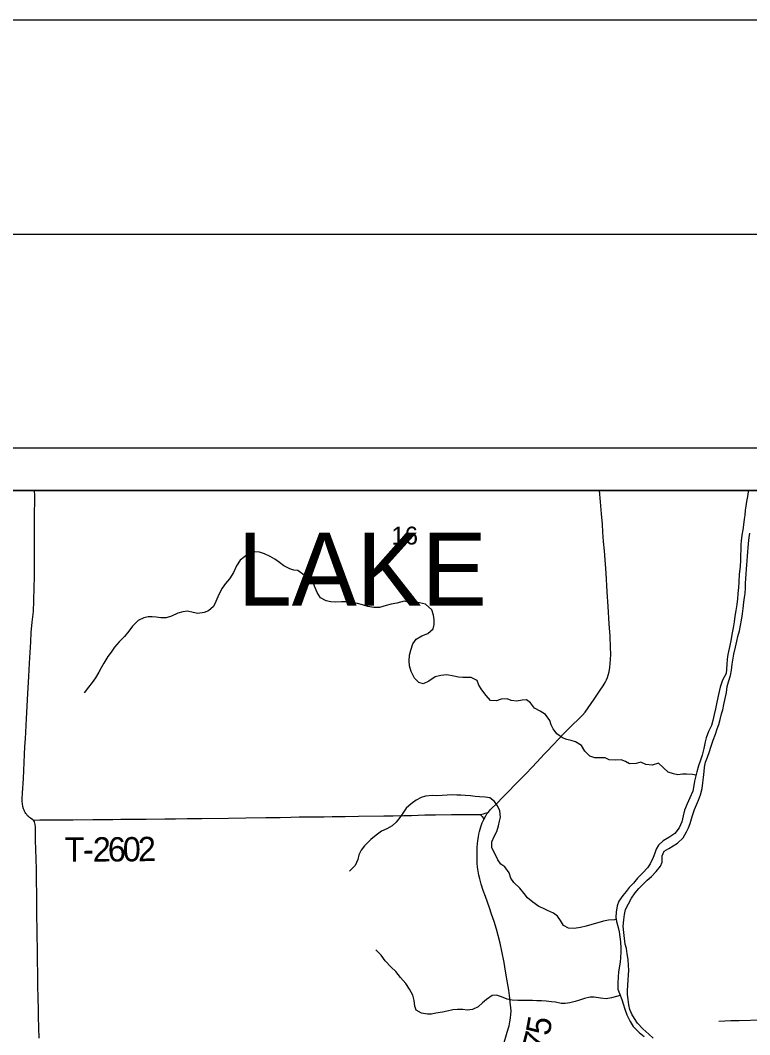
# Model space of a CAD drawing. Extents: x -7.5 to 53.5, y 0 to 22.
# Drawn here: x 6.245 to 7.951, y 19.628 to 22 of the extents above; entities that cross this region are included whole.
import ezdxf

# ---------------------------------------------------------------- set-up
doc = ezdxf.new("R2010")
doc.units = 0
for name, color, linetype in [('GM_X_Corporation', 7, 'Continuous'), ('GM_X_County_Road', 7, 'Continuous'), ('GM_X_County_Road_Text', 7, 'Continuous'), ('GM_X_Major_River', 7, 'Continuous'), ('GM_X_Minor_River', 7, 'Continuous'), ('GM_X_Section_Text', 7, 'Continuous'), ('GM_X_Township_Road', 7, 'Continuous'), ('GM_X_Township_Road_Text', 7, 'Continuous'), ('GM_X_Township_Text', 7, 'Continuous'), ('SH_Border', 7, 'Continuous'), ('SH_Cut_Line', 7, 'Continuous'), ('SH_Data', 7, 'Continuous')]:
    doc.layers.add(name, color=color, linetype=linetype)

msp = doc.modelspace()

# ---------------------------------------------------------------- linework, layer by layer
at = {"layer": 'GM_X_Corporation'}
msp.add_lwpolyline([(4.6087, 14.5302), (4.6021, 15.6139), (4.594, 15.8096), (4.5873, 16.3533), (4.5872, 16.3635), (4.5826, 16.8462), (4.5822, 16.8992), (4.577, 17.1178), (4.5749, 17.2575), (4.5771, 17.6201), (4.5718, 18.1276), (4.5696, 18.2604), (4.5565, 19.1354), (5.0411, 19.1401), (6.0424, 19.1527), (6.0433, 19.1527), (6.5522, 19.1561), (7.544, 19.1455), (8.414, 19.1709), (8.5159, 19.1718), (8.9, 19.1887), (8.9, 20.9), (2.1, 20.9), (2.1, 14.1)], dxfattribs=at)
at = {"layer": 'GM_X_County_Road'}
for points in [[(7.3398, 20.1485), (7.3439, 20.1533), (7.348, 20.1575), (7.3577, 20.1672), (7.375, 20.1846), (7.3861, 20.1954), (7.4034, 20.2133), (7.4163, 20.2267), (7.4269, 20.2379), (7.4418, 20.2536), (7.4631, 20.2759), (7.4693, 20.2826), (7.4755, 20.2893), (7.4925, 20.3071), (7.5032, 20.3182), (7.5139, 20.3294), (7.5248, 20.3405), (7.5357, 20.3514), (7.5512, 20.3664), (7.5598, 20.3753), (7.5658, 20.3823), (7.5733, 20.3922), (7.5875, 20.4125), (7.6014, 20.4331), (7.6084, 20.4435), (7.6132, 20.4517), (7.6158, 20.4572), (7.618, 20.463), (7.62, 20.4688), (7.6219, 20.4763), (7.6237, 20.4861), (7.6249, 20.4959), (7.6256, 20.5052), (7.6258, 20.5176), (7.6254, 20.533), (7.6244, 20.5599), (7.6224, 20.5889), (7.6198, 20.6292), (7.6177, 20.6633), (7.6151, 20.7067), (7.6113, 20.7594), (7.6093, 20.781), (7.6076, 20.8027), (7.6063, 20.8213), (7.6042, 20.846), (7.6017, 20.8739), (7.5994, 20.9)], [(7.3287, 20.1306), (7.3336, 20.1398), (7.3364, 20.1439), (7.3398, 20.1485)], [(7.3748, 19.6041), (7.3839, 19.6335), (7.3882, 19.6488), (7.3901, 19.6579), (7.3915, 19.6666), (7.3924, 19.676), (7.3926, 19.6831), (7.3923, 19.6916), (7.391, 19.7029), (7.3897, 19.7132), (7.3872, 19.7315), (7.3821, 19.7626), (7.378, 19.7865), (7.3763, 19.7963), (7.371, 19.8232), (7.3672, 19.8414), (7.3629, 19.8595), (7.3589, 19.8744), (7.3534, 19.8921), (7.3473, 19.9097), (7.342, 19.9242), (7.3326, 19.9506), (7.3275, 19.9653), (7.3228, 19.98), (7.3195, 19.992), (7.3174, 20.0011), (7.3157, 20.0103), (7.3144, 20.0196), (7.3137, 20.0289), (7.3133, 20.0414), (7.3134, 20.0538), (7.3138, 20.0663), (7.3148, 20.0817), (7.3163, 20.0905), (7.3174, 20.0967), (7.3191, 20.1029), (7.3204, 20.1087), (7.3221, 20.1141), (7.3254, 20.1232), (7.3274, 20.1277), (7.3287, 20.1306)]]:
    msp.add_lwpolyline(points, dxfattribs=at)
at = {"layer": 'GM_X_Major_River'}
for points in [[(7.9476, 20.9), (7.9471, 20.8971), (7.9456, 20.8865), (7.9438, 20.8747), (7.9416, 20.8637), (7.9405, 20.8542), (7.9398, 20.8428), (7.9383, 20.833), (7.9361, 20.82), (7.9346, 20.8087), (7.9327, 20.7957), (7.9313, 20.7828), (7.9306, 20.7733), (7.9299, 20.762), (7.9295, 20.7483), (7.9292, 20.7373), (7.9285, 20.7225), (7.9267, 20.7046), (7.9252, 20.6857), (7.9245, 20.6739), (7.9231, 20.6595), (7.9224, 20.6473), (7.9205, 20.6337), (7.9187, 20.6196), (7.9165, 20.6067), (7.9146, 20.593), (7.912, 20.579), (7.9094, 20.5638), (7.9065, 20.5486), (7.9028, 20.5307), (7.9002, 20.5171), (7.8979, 20.5061), (7.8972, 20.4932), (7.8958, 20.4723), (7.8875, 20.4571), (7.8819, 20.4407), (7.8793, 20.4301), (7.8763, 20.4164), (7.8734, 20.4012), (7.8711, 20.3895), (7.8678, 20.3765), (7.8648, 20.3621), (7.8618, 20.3511), (7.8547, 20.3366), (7.8494, 20.3222), (7.8468, 20.3127), (7.8435, 20.2967), (7.8394, 20.2816), (7.836, 20.2698), (7.8315, 20.2561), (7.8274, 20.2428), (7.824, 20.2303), (7.8222, 20.2208), (7.8203, 20.2105), (7.8181, 20.1972), (7.811, 20.1816), (7.805, 20.1676), (7.7986, 20.1527), (7.7952, 20.1395), (7.7919, 20.1254), (7.7859, 20.1117), (7.7761, 20.098), (7.7617, 20.0885), (7.7489, 20.0808), (7.7375, 20.0713), (7.7319, 20.0618)], [(7.7012, 19.979), (7.7113, 19.9889), (7.7212, 19.9976), (7.7325, 20.0094), (7.7423, 20.022), (7.746, 20.0315), (7.7464, 20.0459), (7.7509, 20.0566), (7.7618, 20.0634), (7.7716, 20.0692), (7.7819, 20.0756), (7.7951, 20.0882), (7.803, 20.1019), (7.8079, 20.1118), (7.8116, 20.1217), (7.815, 20.1327), (7.818, 20.1426), (7.8217, 20.154), (7.8262, 20.165), (7.8311, 20.176), (7.8356, 20.1889), (7.8397, 20.2038), (7.8415, 20.217), (7.843, 20.2292), (7.8444, 20.2436), (7.8455, 20.2535), (7.8478, 20.2649), (7.8519, 20.2767), (7.8568, 20.29), (7.8601, 20.3002), (7.8657, 20.3162), (7.8706, 20.3302), (7.8751, 20.3428), (7.8785, 20.3534), (7.8818, 20.3648), (7.8852, 20.3777), (7.8878, 20.3872), (7.8908, 20.4002), (7.8938, 20.4138), (7.8964, 20.4283), (7.8986, 20.4423), (7.9012, 20.4529), (7.9057, 20.4678), (7.9083, 20.4799), (7.9097, 20.4943), (7.9123, 20.508), (7.9142, 20.5179), (7.9175, 20.5338), (7.9209, 20.5483), (7.9235, 20.5589), (7.9268, 20.5722), (7.9291, 20.5843), (7.9317, 20.5969), (7.9343, 20.6117), (7.9357, 20.6242), (7.9376, 20.639), (7.939, 20.65), (7.9401, 20.6595), (7.9408, 20.6721), (7.9415, 20.6834), (7.9423, 20.6941), (7.943, 20.7058), (7.9437, 20.7161), (7.944, 20.7263), (7.9451, 20.7362), (7.9462, 20.7465), (7.9469, 20.7567), (7.9476, 20.7662), (7.948, 20.7761), (7.9498, 20.7901), (7.9513, 20.8004)], [(7.7319, 20.0618), (7.7289, 20.0523), (7.7255, 20.0424), (7.718, 20.0272), (7.712, 20.0177), (7.7007, 20.0059), (7.6882, 19.9941), (7.6788, 19.9823), (7.669, 19.972), (7.6622, 19.9625), (7.6539, 19.953), (7.6452, 19.94), (7.6411, 19.9294), (7.6385, 19.9146), (7.6382, 19.9028), (7.6394, 19.8926), (7.6432, 19.8785), (7.6455, 19.8679), (7.6475, 19.8566), (7.6487, 19.8452), (7.6495, 19.8304), (7.6495, 19.8205), (7.6488, 19.8084), (7.6481, 19.7977), (7.6444, 19.775), (7.6429, 19.762), (7.6422, 19.7484), (7.6423, 19.7343), (7.6461, 19.7237), (7.6519, 19.7097), (7.6553, 19.7002), (7.6588, 19.6873), (7.6634, 19.6745), (7.671, 19.6585), (7.6783, 19.6468), (7.6927, 19.6332), (7.7038, 19.6238)], [(7.7254, 19.6197), (7.7147, 19.6291), (7.701, 19.6412), (7.6885, 19.6548), (7.6816, 19.6654), (7.6751, 19.676), (7.6709, 19.6866), (7.6686, 19.6972), (7.6663, 19.7098), (7.6651, 19.7219), (7.6654, 19.7314), (7.6661, 19.7428), (7.6668, 19.7557), (7.6675, 19.7671), (7.6683, 19.7788), (7.6675, 19.7895), (7.6666, 19.8035), (7.6643, 19.8168), (7.6624, 19.8289), (7.66, 19.8395), (7.6581, 19.8524), (7.6565, 19.8668), (7.6553, 19.8813), (7.6564, 19.8964), (7.6579, 19.9086), (7.6608, 19.9207), (7.6672, 19.934), (7.6744, 19.947), (7.683, 19.9592), (7.6913, 19.9694), (7.7012, 19.979)]]:
    msp.add_lwpolyline(points, dxfattribs=at)
at = {"layer": 'GM_X_Minor_River'}
for points in [[(6.8749, 20.717), (6.8609, 20.7245), (6.8514, 20.7317), (6.8404, 20.7396), (6.829, 20.7464), (6.8157, 20.7521), (6.8043, 20.7558), (6.7937, 20.7573), (6.7816, 20.7535), (6.7695, 20.7454), (6.7593, 20.7371), (6.7506, 20.7241), (6.7435, 20.7089), (6.7337, 20.6941), (6.7246, 20.6827), (6.7171, 20.672), (6.7118, 20.6621), (6.7069, 20.6515), (6.7024, 20.6408), (6.6964, 20.629), (6.6847, 20.6191), (6.6745, 20.6153), (6.6597, 20.6126), (6.6491, 20.6152), (6.6355, 20.6178), (6.6248, 20.617), (6.6131, 20.6135), (6.5987, 20.6063), (6.5862, 20.6028), (6.5737, 20.6028), (6.5627, 20.6039), (6.5533, 20.6046), (6.5438, 20.6049), (6.5336, 20.6026), (6.5207, 20.5965), (6.5071, 20.5828), (6.4985, 20.5717), (6.4883, 20.5592), (6.4758, 20.5462), (6.4653, 20.5341), (6.4573, 20.5226), (6.4494, 20.512), (6.44, 20.4968), (6.434, 20.4854), (6.4287, 20.4755), (6.4208, 20.4625), (6.4125, 20.4511), (6.4046, 20.4405), (6.3941, 20.4275)], [(7.8251, 20.2344), (7.8168, 20.2359), (7.8035, 20.237), (7.7937, 20.2366), (7.7827, 20.2358), (7.7725, 20.2377), (7.7599, 20.2414), (7.7379, 20.2626), (7.7231, 20.258), (7.7079, 20.2598), (7.6962, 20.2651), (7.6856, 20.2616), (7.67, 20.2608), (7.6602, 20.2668), (7.6503, 20.2702), (7.6363, 20.2698), (7.6226, 20.2705), (7.6131, 20.2754), (7.5995, 20.275), (7.5885, 20.2753), (7.5771, 20.2787), (7.5653, 20.2904), (7.5577, 20.3044), (7.5433, 20.3123), (7.5334, 20.3161), (7.5231, 20.3183), (7.5133, 20.3217), (7.5, 20.3311), (7.4912, 20.3429), (7.4866, 20.3527), (7.4832, 20.3622), (7.4736, 20.3769), (7.4607, 20.3845), (7.4478, 20.3916), (7.4383, 20.4041), (7.4288, 20.4106), (7.4189, 20.4101), (7.4064, 20.4074), (7.3932, 20.4089), (7.3837, 20.413), (7.3696, 20.4126), (7.359, 20.4084), (7.3446, 20.4091), (7.3347, 20.4208), (7.3241, 20.4341), (7.3176, 20.4454), (7.3134, 20.456), (7.2997, 20.4628), (7.2898, 20.4632), (7.2796, 20.4631), (7.2701, 20.4638), (7.2588, 20.4665), (7.2428, 20.4691), (7.2281, 20.4675), (7.2148, 20.4644), (7.2001, 20.4545), (7.1868, 20.448), (7.1766, 20.451), (7.1671, 20.4616), (7.159, 20.4767), (7.1552, 20.49), (7.1544, 20.5017), (7.1555, 20.5154), (7.1581, 20.5272), (7.1626, 20.5416), (7.1709, 20.5523), (7.1837, 20.5603), (7.1981, 20.566), (7.2102, 20.5771), (7.2128, 20.5873), (7.2127, 20.598), (7.2112, 20.6086), (7.2073, 20.6215), (7.1929, 20.6347), (7.1788, 20.6373), (7.1694, 20.6377), (7.155, 20.6387), (7.1428, 20.6413), (7.1258, 20.6371), (7.1125, 20.6344), (7.1008, 20.6313), (7.0849, 20.6267), (7.072, 20.627), (7.058, 20.6293), (7.0451, 20.633), (7.0333, 20.636), (7.0189, 20.6386), (7.0071, 20.6401), (6.9962, 20.6397), (6.9825, 20.6396), (6.9708, 20.6403), (6.9601, 20.6426), (6.9468, 20.6493), (6.9388, 20.6615), (6.9331, 20.677), (6.9289, 20.688), (6.9186, 20.6993), (6.9087, 20.7027), (6.8943, 20.7129), (6.8844, 20.7144), (6.8749, 20.717)], [(7.6387, 19.8982), (7.6344, 19.8967), (7.6204, 19.8955), (7.609, 19.8932), (7.5958, 19.8894), (7.5818, 19.8855), (7.5682, 19.8817), (7.5549, 19.8786), (7.5401, 19.8763), (7.5272, 19.8766), (7.5155, 19.8834), (7.5086, 19.8951), (7.5017, 19.905), (7.4922, 19.9121), (7.4782, 19.9185), (7.4683, 19.9227), (7.4577, 19.9276), (7.4436, 19.9374), (7.4314, 19.948), (7.4234, 19.9578), (7.4135, 19.9707), (7.3995, 19.9835), (7.3922, 19.9937), (7.3884, 20.0062), (7.3785, 20.0202), (7.3686, 20.0263), (7.3617, 20.0365), (7.3545, 20.0513), (7.348, 20.0649), (7.3479, 20.0786), (7.3535, 20.0915), (7.3592, 20.1029), (7.3633, 20.1158), (7.3659, 20.1272), (7.3681, 20.1367), (7.3662, 20.1515), (7.3612, 20.1632), (7.354, 20.1731), (7.3429, 20.1818), (7.3323, 20.1832), (7.319, 20.184), (7.3088, 20.1851), (7.2982, 20.1862), (7.2853, 20.1872), (7.2751, 20.188), (7.2656, 20.1879), (7.255, 20.1883), (7.2436, 20.1875), (7.2315, 20.1867), (7.219, 20.1866), (7.2091, 20.1873), (7.1928, 20.1858), (7.1826, 20.1827), (7.1705, 20.1758), (7.1592, 20.1678), (7.1475, 20.1571), (7.1396, 20.1461), (7.1328, 20.1354), (7.1241, 20.1248), (7.1143, 20.116), (7.1022, 20.1095), (7.0897, 20.1034), (7.0773, 20.0946), (7.0648, 20.084), (7.0497, 20.0691), (7.0418, 20.0592), (7.0365, 20.0482), (7.0343, 20.0375), (7.0283, 20.0231), (7.0151, 20.0105)], [(7.6479, 19.7195), (7.6393, 19.7172), (7.628, 19.7142), (7.6155, 19.7118), (7.6018, 19.7129), (7.5874, 19.7152), (7.5779, 19.7151), (7.5643, 19.7124), (7.5526, 19.7086), (7.5427, 19.7051), (7.5302, 19.702), (7.5193, 19.7005), (7.5098, 19.7008), (7.4965, 19.7034), (7.487, 19.7045), (7.4745, 19.706), (7.4639, 19.7071), (7.4529, 19.7071), (7.4427, 19.7078), (7.418, 19.7077), (7.4086, 19.708), (7.3953, 19.7087), (7.3835, 19.7106), (7.3706, 19.7166), (7.3585, 19.72), (7.3483, 19.7192), (7.3354, 19.7104), (7.3256, 19.7024), (7.3154, 19.6929), (7.3029, 19.6868), (7.2904, 19.6852), (7.2798, 19.6863), (7.2673, 19.687), (7.2567, 19.6862), (7.2431, 19.6831), (7.2321, 19.6804), (7.2169, 19.6777), (7.2067, 19.6761), (7.1969, 19.6757), (7.1832, 19.678), (7.1707, 19.6851), (7.1676, 19.6946), (7.166, 19.7075), (7.1626, 19.7204), (7.1553, 19.7344), (7.1462, 19.7476), (7.134, 19.7616), (7.1233, 19.7753), (7.1123, 19.7858), (7.0986, 19.8002), (7.089, 19.8135), (7.0761, 19.8263)]]:
    msp.add_lwpolyline(points, dxfattribs=at)
at = {"layer": 'GM_X_Township_Road'}
for points in [[(6.2749, 20.1291), (6.2738, 20.1301), (6.2687, 20.1337), (6.2663, 20.1356), (6.264, 20.1377), (6.2618, 20.1399), (6.2598, 20.1423), (6.2579, 20.1448), (6.2563, 20.1474), (6.2548, 20.1501), (6.2534, 20.1529), (6.2523, 20.1558), (6.2505, 20.1617), (6.2495, 20.1679), (6.2491, 20.1741), (6.2492, 20.1803), (6.2498, 20.1927), (6.2519, 20.2268), (6.2536, 20.264), (6.2556, 20.3013), (6.2567, 20.3199), (6.259, 20.3664), (6.2624, 20.4254), (6.2646, 20.4657), (6.2663, 20.4967), (6.269, 20.5464), (6.2705, 20.5681), (6.2728, 20.5928), (6.2752, 20.6176), (6.2764, 20.6424), (6.2774, 20.6734), (6.2776, 20.6983), (6.2778, 20.7355), (6.278, 20.7634), (6.2781, 20.8036), (6.2782, 20.8532), (6.2784, 20.8688), (6.2785, 20.8828), (6.2784, 20.8904), (6.2783, 20.8977), (6.2782, 20.9)], [(6.2749, 20.1291), (6.2902, 20.1298), (6.2996, 20.1302), (6.3244, 20.1301), (6.368, 20.1302), (6.4146, 20.1308), (6.4613, 20.1311), (6.4799, 20.1315), (6.5079, 20.1318), (6.539, 20.1319), (6.5825, 20.1325), (6.6074, 20.1328), (6.6353, 20.1332), (6.6695, 20.1336), (6.7317, 20.1342), (6.7721, 20.1346), (6.8187, 20.1353), (6.8529, 20.136), (6.8777, 20.1366), (6.8973, 20.137), (6.9217, 20.1372), (6.9378, 20.1373), (6.9553, 20.1375), (6.9739, 20.1376), (7.005, 20.1383), (7.036, 20.1387), (7.0949, 20.1395), (7.1166, 20.1398), (7.1415, 20.1402), (7.1602, 20.1406), (7.1912, 20.1415), (7.2037, 20.1418), (7.2161, 20.1421), (7.2532, 20.1425), (7.2935, 20.1426), (7.3028, 20.1424), (7.319, 20.143)], [(7.319, 20.143), (7.3244, 20.1436), (7.3279, 20.1443), (7.3318, 20.1456), (7.3359, 20.1469), (7.3398, 20.1485)], [(7.319, 20.143), (7.3215, 20.1416), (7.3238, 20.1399), (7.3253, 20.1379), (7.3273, 20.1348), (7.3287, 20.1306)], [(6.2886, 19.6195), (6.2876, 19.6692), (6.2874, 19.6878), (6.2867, 19.7127), (6.2861, 19.7438), (6.2847, 19.8277), (6.2841, 19.8587), (6.2839, 19.8742), (6.2835, 19.9053), (6.2835, 19.9208), (6.2832, 19.955), (6.2827, 19.9892), (6.2825, 20.0109), (6.2816, 20.0419), (6.2812, 20.0574), (6.2805, 20.0854), (6.2799, 20.1134), (6.2794, 20.1196), (6.2788, 20.1226), (6.2778, 20.1255), (6.2761, 20.128), (6.2749, 20.1291)], [(7.8786, 19.6593), (7.9072, 19.6608), (7.9267, 19.6612), (7.9789, 19.6625)]]:
    msp.add_lwpolyline(points, dxfattribs=at)
at = {"layer": 'SH_Border'}
msp.add_lwpolyline([(1.5, 21.5), (33.5, 21.5), (33.5, 0.5), (1.5, 0.5)], close=True, dxfattribs=at)
at = {"layer": 'SH_Cut_Line'}
msp.add_lwpolyline([(0, 0), (34, 0), (34, 22), (0, 22)], close=True, dxfattribs=at)
at = {"layer": 'SH_Data'}
for p, q in [((2, 21), (9, 21)), ((2.1, 20.9), (8.9, 20.9))]:
    msp.add_line(p, q, dxfattribs=at)

# ---------------------------------------------------------------- texts
at = {"layer": 'GM_X_County_Road_Text'}
for s, rotation, p in [('5', 79.6224, (7.4824, 19.6233)), ('7', 75.4023, (7.4726, 19.5849))]:
    msp.add_text(s, height=0.0568, rotation=rotation, dxfattribs=at).set_placement(p)
at = {"layer": 'GM_X_Section_Text'}
msp.add_text('16', height=0.04186, rotation=0, dxfattribs=at).set_placement((7.1128, 20.774))
at = {"layer": 'GM_X_Township_Road_Text'}
for s, rotation, p in [('T', 0.2443, (6.3486, 20.0323)), ('2', 0.2592, (6.4144, 20.0326)), ('6', 0.3078, (6.4495, 20.0327)), ('0', 0.4521, (6.4846, 20.0329)), ('2', 1.169, (6.5204, 20.0332)), ('-', 0.2557, (6.3911, 20.0325))]:
    msp.add_text(s, height=0.0568, rotation=rotation, dxfattribs=at).set_placement(p)
at = {"layer": 'GM_X_Township_Text'}
msp.add_text('LAKE', height=0.17045, rotation=0, dxfattribs=at).set_placement((6.753, 20.6314))

doc.saveas('drawing.dxf')
